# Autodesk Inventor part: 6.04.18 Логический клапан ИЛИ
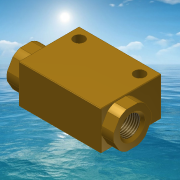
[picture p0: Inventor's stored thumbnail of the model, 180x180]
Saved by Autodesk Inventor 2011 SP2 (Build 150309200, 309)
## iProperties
Created: 2011-08
Part Number: 6.04.18 Логический клапан ИЛИ
Document SubType Name: Modeling
Designer: khramov
Density: 2.71 g/cm^3
Material: Алюминий - 6061
Mass: 33.1203 g
Surface Area: 55.9448 cm^2
Volume: 12.2215 cm^3
Author: khramov
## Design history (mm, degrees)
sketch "Эскиз1"
  geometry: L1 (0, 0)-(34, 0); L2 (34, 0)-(34, -25); L3 (34, -25)-(0, -25); L4 (0, -25)-(0, 0)
  constraints: 8 end point, 2 parallel, 1 horizontal, 1 perpendicular
  dimensions: "d0" = 34 distance of L1.start L1.end; "d1" = 25 distance of L3.end L1.start
extrude "Выдавливание1" new body sketch "Эскиз1" distance "d2" = 16; taper "d3" = 0 deg
sketch "Эскиз2"
  geometry: L1 (0, 0)-(-16, 0) reference; L2 (-8, -0.66)-(-15.5, 3.67); L3 (-15.5, 3.67)-(-15.5, 12.33); L4 (-15.5, 12.33)-(-8, 16.66); L5 (-8, 16.66)-(-0.5, 12.33); L6 (-0.5, 12.33)-(-0.5, 3.67); L7 (-0.5, 3.67)-(-8, -0.66); L8 (-16, 25)-(-16, 0) reference; L9 (0, 25)-(0, 0) reference; 1 further point
  constraints: 12 end point, 13 other
  dimensions: "d4" = 15 distance between parallel lines of L6 L3; "d5" = 8 distance from line of point (-8, 8) L1; "d38" = 8 distance from line of L8 point (-8, 8) (= d39); "d39" = 8 distance from line of L9 point (-8, 8) (derived)
extrude "Выдавливание2" join sketch "Эскиз2" distance "d6" = 5; taper "d7" = 0 deg
sketch "Эскиз3"
  geometry: L1 (0, 0)-(16, 0) reference; L2 (8, 16.66)-(15.5, 12.33); L3 (15.5, 12.33)-(15.5, 3.67); L4 (15.5, 3.67)-(8, -0.66); L5 (8, -0.66)-(0.5, 3.67); L6 (0.5, 3.67)-(0.5, 12.33); L7 (0.5, 12.33)-(8, 16.66); L8 (16, 0)-(16, 25) reference; L9 (0, 0)-(0, 25) reference; 1 further point
  constraints: 12 end point, 13 other
  dimensions: "d8" = 15 distance between parallel lines of L6 L3; "d9" = 8 distance from line of L1 point (8, 8); "d40" = 8 distance from line of point (8, 8) L9 (= d41); "d41" = 8 distance from line of L8 point (8, 8) (derived)
extrude "Выдавливание3" join sketch "Эскиз3" distance "d10" = 5; taper "d11" = 0 deg
sketch "Эскиз4"
  geometry: L1 (0, 0)-(34, 0) reference; L2 (34, 0)-(34, -25) reference; L3 (0, -25)-(0, 0) reference; C1 r 2.25 at (4.5, -4.5); C2 r 2.25 at (29.5, -4.5)
  constraints: 2 centre point
  dimensions: "d12" = 4.5 diameter of C2 (= d13); "d13" = 4.5 diameter of C1; "d46" = 4.5 distance from line of C1.centre L3 (= d49); "d47" = 25 distance of C2.centre C1.centre; "d48" = 0 vertical distance of C1.centre C2.centre; "d49" = 4.5 distance from line of L2 C2.centre (derived); "d50" = 4.5 distance from line of C1.centre L1
extrude "Выдавливание4" cut sketch "Эскиз4" stored distance "d15" = 6; taper "d16" = 0 deg
sketch "Эскиз5"
  geometry: L1 (34, 0)-(34, -16) reference; L2 (0, 0)-(34, 0) reference; L3 (34, 0)-(0, 0) reference; L4 (34, -16)-(0, -16) reference; L5 (0, 0)-(0, -16) reference; 3 further points
  dimensions: "d42" = 8 distance from line of L2 point (17, -8) (= d43); "d43" = 8 distance from line of L4 point (17, -8) (derived); "d44" = 17 distance from line of L5 point (17, -8) (= d45); "d45" = 17 distance from line of L1 point (17, -8) (derived)
hole "Отверстие1" sketch "Эскиз5" at (17, -8) diameter "d17" = 8.566; stored, may be unused: countersink angle "d21" = 90 deg, drill point angle "d23" = 118 deg; dims "d18" = 10, "d19" = 13, "d20" = 0.5, "d22" = 13
sketch "Эскиз6"
  geometry: L1 (-15.5, 3.67)-(-15.5, 12.33) reference; L2 (-8, 16.66)-(-0.5, 12.33) reference; L3 (-15.5, 12.33)-(-8, 16.66) reference; C1 r 7.5 at (-8, 8); 2 further points
  constraints: 3 tangent, 1 centre point, 1 coincident
hole "Отверстие2" sketch "Эскиз6" at (-8, 8) diameter "d24" = 8.566; stored, may be unused: countersink angle "d28" = 90 deg, drill point angle "d30" = 118 deg; dims "d25" = 10, "d26" = 10.5, "d27" = 2, "d29" = 15
sketch "Эскиз7"
  geometry: L1 (8, 16.66)-(15.5, 12.33) reference; L2 (0.5, 12.33)-(8, 16.66) reference; L3 (0.5, 3.67)-(0.5, 12.33) reference; C1 r 7.5 at (8, 8); 2 further points
  constraints: 3 tangent, 1 centre point, 1 coincident
hole "Отверстие3" sketch "Эскиз7" at (8, 8) diameter "d31" = 8.566; stored, may be unused: countersink angle "d35" = 90 deg, drill point angle "d37" = 118 deg; dims "d32" = 10, "d33" = 10.5, "d34" = 2, "d36" = 15
sketch "Эскиз8"
  geometry: C1 r 5.25 at (-8, 8) reference; C2 r 15 at (-8, 8); C3 r 7.85 at (-8, 8); 1 further point
  constraints: 2 centre point, 1 coincident
  dimensions: "d51" = 30 diameter of C2; "d52" = 15.7 diameter of C3; "d53" = 0 distance of C3.centre C1.centre; "d54" = 0 distance of C2.centre C1.centre
extrude "Выдавливание5" cut sketch "Эскиз8" distance "d55" = 5; taper "d56" = 0 deg
sketch "Эскиз9"
  geometry: C1 r 5.25 at (8, 8) reference; C2 r 15 at (8, 8); C3 r 7.85 at (8, 8); 1 further point
  constraints: 2 centre point, 1 coincident
  dimensions: "d57" = 30 diameter of C2; "d58" = 15.7 diameter of C3; "d59" = 0 distance of C3.centre C1.centre; "d60" = 0 distance of C2.centre C1.centre
extrude "Выдавливание6" cut sketch "Эскиз9" distance "d61" = 5; taper "d62" = 0 deg
chamfer "Фаска1" distance "d63" = 1; stored, may be unused: second distance "d64" = 2, angle "d65" = 45 deg
chamfer "Фаска2" distance "d66" = 0.2; stored, may be unused: second distance "d67" = 2, angle "d68" = 45 deg
node "Твердое тело1"
